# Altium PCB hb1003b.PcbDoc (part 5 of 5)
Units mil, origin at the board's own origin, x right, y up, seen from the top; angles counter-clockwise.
Board outline 2757 x 3548 mil, 2 copper layers (Top Layer, Bottom Layer); 120 components, 120 nets, 466 pads, 329 vias.
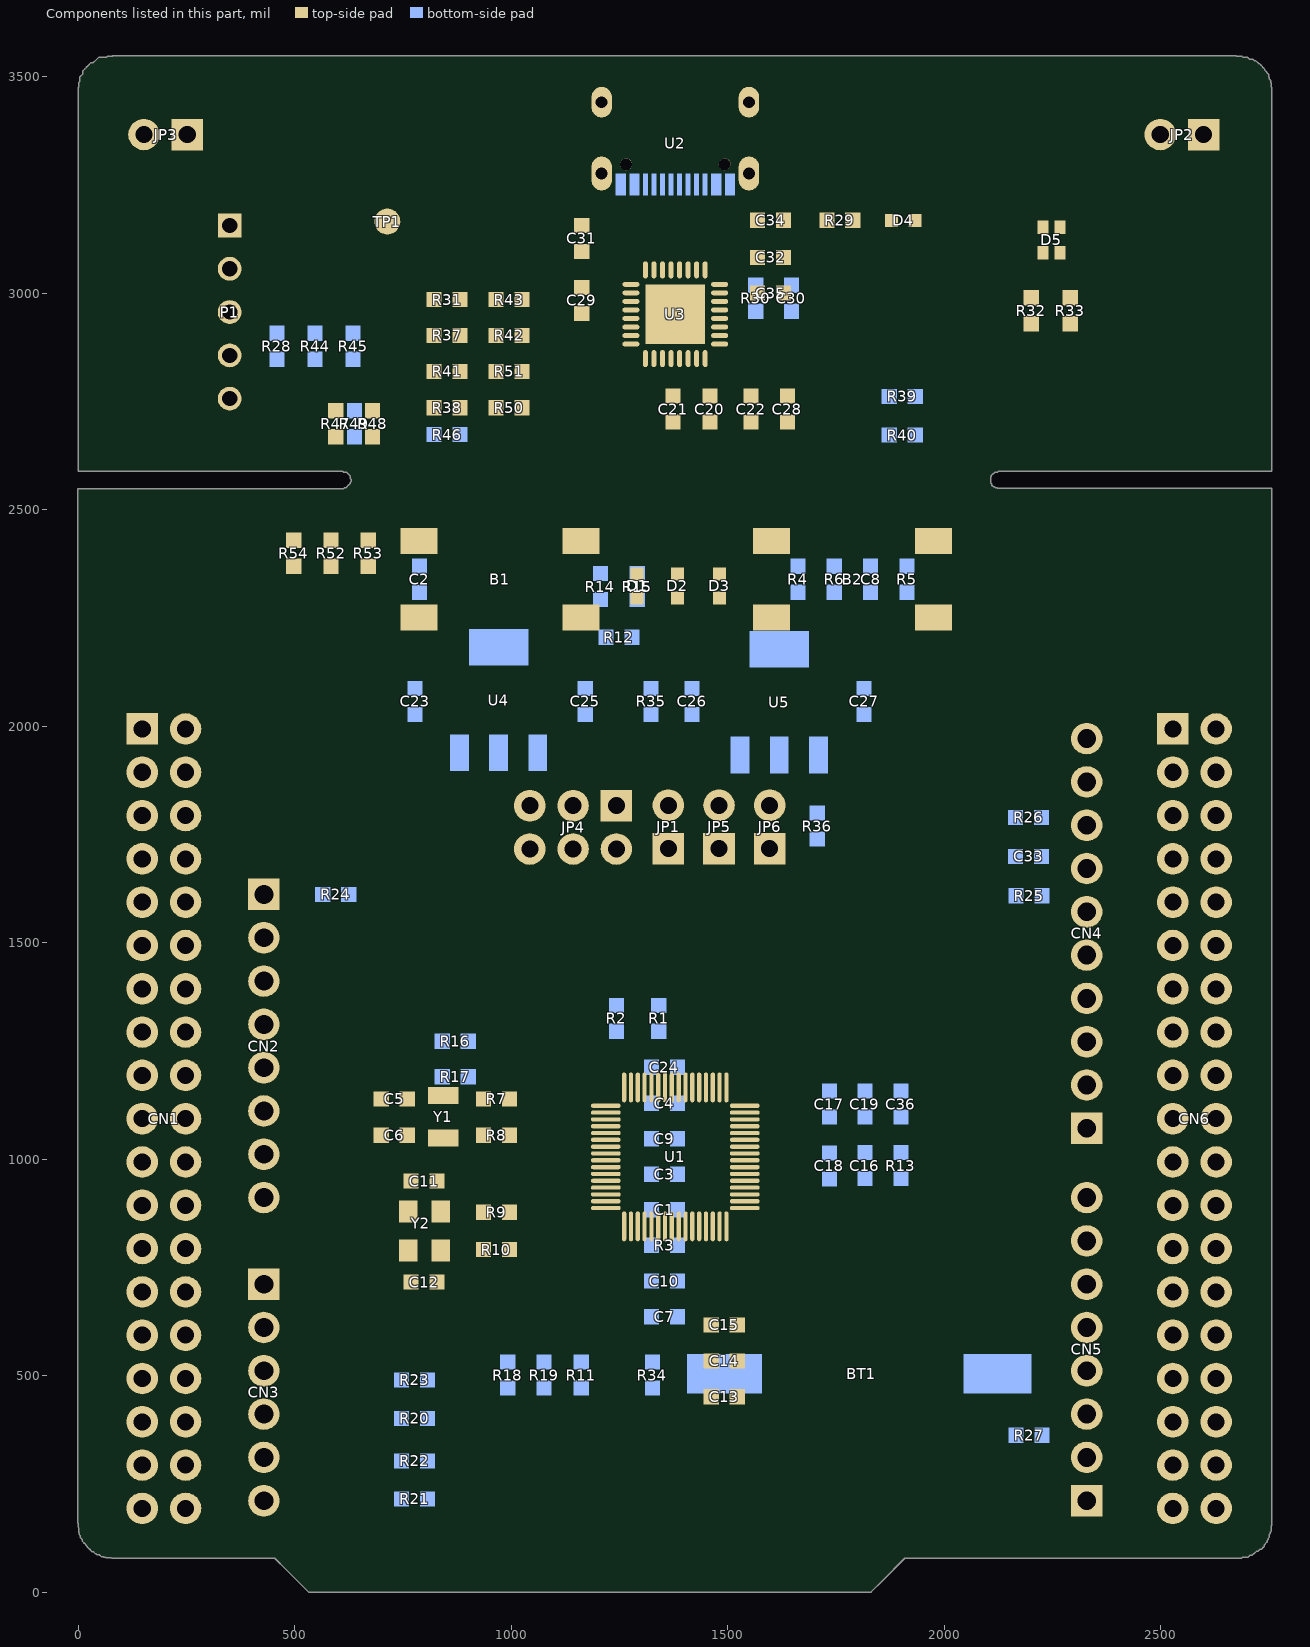
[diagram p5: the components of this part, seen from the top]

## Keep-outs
Keep-Out Layer:
  lines w5: -1,2549 612,2549 ; 0.05,2550 0.05,156.99 ccw(c78.79,156.99) 78.79,78.25 447.69,78.25 452.81,78.25 531.55,-0.49 1830.76,-0.49 ; 609.63,2548.62 ccw(c610.29,2568.3) 610.61,2587.98 ; 610.29,2548.61 ccw(c610.29,2568.29) 610.29,2587.98 ; 611,2588 0,2588 0.05,3468.81 ; 743,2587.98 1495,2587.98 ; 745,2548.61 1497,2548.61 ; 747.77,2548.61 cw(c748.09,2568.29) 748.74,2587.97 ; 748.09,2548.61 cw(c748.09,2568.29) 748.09,2587.98 ; 1496.12,2548.62 ccw(c1496.78,2568.3) 1497.09,2587.98 ; 1677.03,2548.61 cw(c1677.35,2568.29) 1678.01,2587.97 ; 1678,2587.98 1966,2587.98 ; 1679,2548.61 1967,2548.61 ; 1908.32,78.25 2677.22,78.25 ccw(c2677.22,156.99) 2755.96,156.99 2755.96,2548 ; 1909.5,78.25 1830.76,-0.49 ; 1966.59,2548.62 ccw(c1967.25,2568.3) 1967.56,2587.98 ; 2125,2548.61 2753,2548.61 ; 2125.06,2548.61 cw(c2125.38,2568.29) 2126.04,2587.96 ; 2128,2587.98 2756,2587.98 ; 2755.96,2588 2755.96,3468.81 ; 0.05,3468.81 cw(c78.79,3468.81) 78.79,3547.55 ; 0.05,3468.81 cw(c78.79,3468.81) 78.79,3547.55 ; 78.79,3547.55 2677.22,3547.55 ; 1830.76,-0.49 1830.76,-0.49 ; 2677.22,3547.55 cw(c2677.22,3468.81) 2755.96,3468.81 ; 2677.22,3547.55 cw(c2677.22,3468.81) 2755.96,3468.81

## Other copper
Top Layer:
  rectangle net VDD_LINK: 2215,3136 2280,3168
Bottom Layer:
  rectangle net VBUS_5V: 1275,3224 1292,3275
  rectangle net VBUS_5V: 1465,3224 1482,3275
  rectangle net GND: 1497,3225 1514,3276
  rectangle net GND: 1245,3224 1262,3275

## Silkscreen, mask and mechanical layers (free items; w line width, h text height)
Top Overlay:
  lines w5: 488,161 609,161 609,408 ; 488,761 609,761 609,534 ; 492.32,1351 609,1351 609,1221 ; 493,861 609,861 609,1004 ; 888.75,2196.33 1870,2196.33 1870,1876 889,1876 889,2196.33 ; 1341,1640 1653,1640 ; 1649,1640 1693,1640 1693,1768 ; 1694,1768 2006,1768
  text "GND" at 149,3257 h39.37
  text "GND" at 2500,3257 h39.37
  text "LED5" at 2192,3185 h40
  text "VCC" at 98,3134 h40
  text "LED4" at 1844,3067 h40
  text "GND" at 99,3040 h40
  text "SWDIO" at 99,2934 h40
  text "SWCLK" at 98,2834 h40
  text "NRST" at 100,2736 h40
  text "SWD" at 295,2639 h40
  text "LED3" at 1460,2520 h40 r270
  text "LED2" at 1272,2518 h40 r270
  text "LED1" at 1363,2518 h40 r270
  text "RESET" at 909,2476 h40
  text "USER" at 1730,2476 h40
  text "LITE-64" at 467,2239 h40
  text "HB1003B" at 467,2132 h40
  text "SCL/D15" at 2045.22,1948 h40
  text "SDA/D14" at 2065,1852 h35
  text "AREF" at 2154,1751 h35
  text "GND" at 2165.78,1649 h40
  text "E5V" at 1020,1628 h40 r270
  text "VIN5V" at 1116,1628 h40 r270
  text "VBUS" at 1221,1628 h40 r270
  text "BOOT0" at 1339,1628 h40 r270
  text "3V3" at 1456,1628 h40 r270
  text "IDD" at 1576,1628 h40 r270
  text "SCK/D13" at 2036.9,1550 h40
  text "IOREF" at 503,1489 h40
  text "MISO/D12" at 2023.24,1448.5 h40
  text "NRST" at 503,1389 h40
  text "PWM/MOSI/D11" at 1886.46,1350 h40
  text "3V3" at 503,1291 h40
  text "PWM/CS/D10" at 1919.6,1249 h40
  text "5V" at 503,1189 h40
  text "PWM/D9" at 2055.57,1151 h40
  text "GND" at 503,1088 h40
  text "D8" at 2207,1049 h40
  text "POWER" at 655,1016 h40 r90
  text "GND" at 503,990 h40
  text "VIN" at 503,889.09 h40
  text "D7" at 2206.58,888 h40
  text "PWM/D6" at 2055.57,792 h40
  text "PWM/D5" at 2053.66,693 h40
  text "A0" at 503,690 h40
  text "A1" at 503,590 h40
  text "D4" at 2205.68,588 h40
  text "PWM/D3" at 2053.66,490 h40
  text "A2" at 503,489 h40
  text "AIN" at 627,427 h40 r90
  text "A3" at 503,389 h40
  text "D2" at 2207.58,389 h40
  text "TX/D1" at 2127.36,293.72 h40
  text "A4" at 503,289 h40
  text "RX/D0" at 2106.03,192.41 h40
  text "A5" at 503,190 h40
Bottom Overlay:
  lines w5: 1358.9,1721.05 1370.9,1721.05 ; 1639.95,1808.01 1639.95,1820.01 ; 1665.88,1846.05 1677.88,1846.05
  text "PC12" at 118,2036 h35 r45
  text "PD2" at 379.93,2010 h35 r45
  text "PC8" at 2751,2006 h35 r45
  text "PC9" at 2471,2000 h35 r45
  text "PC10" at 118,1934 h35 r45
  text "PC11" at 390.07,1921 h35 r45
  text "PC6" at 2751,1904 h35 r45
  text "PB8" at 2471,1899 h35 r45
  text "VMCU" at 118,1831 h35 r45
  text "E_5V" at 401.73,1820 h35 r45
  text "PC7" at 2751,1797 h35 r45
  text "PB9" at 2471,1792 h35 r45
  text "PA13" at 118,1736 h35 r45
  text "GND" at 2751,1705 h35 r45
  text "PA14" at 382.85,1704 h35 r45
  text "PA0" at 2471,1700 h35 r45
  text "GND" at 99.85,1612 h35 r45
  text "PA15" at 381.67,1612 h35 r45
  text "VBUS" at 2751,1603 h35 r45
  text "AGND" at 2471,1587 h35 r45
  text "3V3" at 381.67,1511 h35 r45
  text "PD1" at 86.66,1502 h35 r45
  text "PC0" at 2751,1500 h35 r45
  text "PA5" at 2471,1495 h35 r45
  text "NRST" at 384.26,1411 h35 r45
  text "PD0" at 97.26,1409 h35 r45
  text "PC1" at 2751,1400 h35 r45
  text "PA6" at 2471,1395 h35 r45
  text "3V3" at 381.67,1310 h35 r45
  text "PD3" at 97.26,1309 h35 r45
  text "PC3" at 2751,1302 h35 r45
  text "PA7" at 2471,1297 h35 r45
  text "5V" at 381.67,1212 h35 r45
  text "PD4" at 98.44,1208 h35 r45
  text "PC4" at 2751,1200 h35 r45
  text "PB0" at 2471,1195 h35 r45
  text "GND" at 382.53,1113 h35 r45
  text "GND" at 99.85,1112 h35 r45
  text "GND" at 2751,1104 h35 r45
  text "PB1" at 2471,1099 h35 r45
  text "GND" at 382.53,1007 h35 r45
  text "PB7" at 97.26,1006 h35 r45
  text "PB6" at 2751,999 h35 r45
  text "PA9" at 2471,994 h35 r45
  text "PC13" at 118,932 h35 r45
  text "VIN" at 382.53,903 h35 r45
  text "PB2" at 2751,902 h35 r45
  text "PA8" at 2471,898 h35 r45
  text "PC15" at 118,836 h35 r45
  text "PD5" at 379.93,810 h35 r45
  text "PB15" at 2751,798 h35 r45
  text "PB14" at 2471,793 h35 r45
  text "PC14" at 118,738 h35 r45
  text "PA1" at 371.92,707 h35 r45
  text "PB13" at 2751,698 h35 r45
  text "PB5" at 2471,693 h35 r45
  text "PA2" at 382.53,612 h35 r45
  text "PF1" at 82.77,601 h35 r45
  text "PB12" at 2751,597 h35 r45
  text "PB4" at 2471,592 h35 r45
  text "PA3" at 382.53,509 h35 r45
  text "PF0" at 93.37,508 h35 r45
  text "AGND" at 2751,503 h35 r45
  text "PB3" at 2471,498 h35 r45
  text "VBAT" at 118,432 h35 r45
  text "PA4" at 383.7,411 h35 r45
  text "PA10" at 2471,403 h35 r45
  text "PA0" at 2751,403 h35 r45
  text "PB10" at 382.53,313 h35 r45
  text "PC2" at 99.85,312 h35 r45
  text "PA11" at 2471,304 h35 r45
  text "VLCD" at 2751,304 h35 r45
  text "PB11" at 382.53,211 h35 r45
  text "PC5" at 99.85,210 h35 r45
  text "GND" at 2751,204 h35 r45
  text "PA12" at 2471,198 h35 r45
Mechanical 1:
  lines w5: 0.05,2243.67 0.05,157.05 ccw(c78.79,157.05) 78.79,78.31 447.69,78.32 452.81,78.32 531.55,-0.43 1830.76,-0.43 ; 0.05,2589 0.05,3468.87 ; 78.79,3548.61 2677.22,3548.61 ; 1908.32,78.31 2677.22,78.31 ccw(c2677.22,157.05) 2755.96,157.05 2755.96,2243.67 ; 1909.5,78.32 1830.76,-0.43 ; 2755.96,2589 2755.96,3468.87 ; 0.05,3468.87 cw(c78.79,3468.87) 78.79,3547.61 ; 0.05,3468.87 cw(c78.79,3468.87) 78.79,3547.61 ; 78.79,3547.61 2677.22,3547.61 ; 78.79,3547.61 2677.22,3547.61 ; 1830.76,-0.43 1830.76,-0.43 ; 2677.22,3547.61 cw(c2677.22,3468.87) 2755.96,3468.87 ; 2677.22,3547.61 cw(c2677.22,3468.87) 2755.96,3468.87

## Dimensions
0.05,3468.81 to 2755.96,3468.81 on Drill Drawing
